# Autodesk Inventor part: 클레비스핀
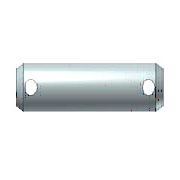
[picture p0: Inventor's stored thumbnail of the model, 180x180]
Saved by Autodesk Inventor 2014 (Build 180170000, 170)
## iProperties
IsCustomPart: 1
Created: 2012-02
Part Number: 클레비스핀
Material: 강철
Description: 머리가 없는 클레비스 핀 B
Document SubType Name: Modeling
Standard: ISO 2340
Designer: mduedu
Standard Revision: Second edition 1986-11-01
Standards Organization: ISO
Language: ko-KR
Size Designation: B - 8 x 45
Categories: <MemberInstance><Categories><Category DisplayName="조임쇠" InternalName="e4da775c-781d-43d5-af7c-5136215cf5a6" Mnemonic="FSTN"><Category DisplayName="핀" InternalNa
Density: 7.85 g/cm^3
Appearance: Steel
Author: mduedu
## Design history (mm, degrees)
sketch "스케치1"
  geometry: L1 (-4.5, 0)-(-4.5, 4); L2 (-4.5, 4)-(40.5, 4); L3 (40.5, 4)-(40.5, 0); L4 (-4.5, 0)-(40.5, 0); L5 (0, -1.46)-(0, 3.16) reference; L6 (-6.4, 0)-(18.8, 0) reference; C1 r 1 at (-1, 0); C2 r 1 at (37, 0)
  constraints: 8 end point, 2 centre point, 2 perpendicular, 2 point on line, 1 collinear, 1 parallel, 1 tangent, 1 vertical
  dimensions: "d0" = 8 diameter of L2 L4 (= NND); "d1" = 45 distance of L1.end L2.end (= NLG); "d2" = 3.5 distance from line of L1 C1.centre (= DIST1); "d3" = 3.5 distance from line of L3 C2.centre (= DIST2); "d4" = 2 diameter of C1 (= BOR1); "d5" = 2 diameter of C2 (= BOR2)
revolve "본체" stored, may be unused: angle "d7" = 90 deg
extrude "구멍1" cut sketch "스케치1" taper "d6" = 0 deg; stored distance "d8" = 10
extrude "구멍2" cut sketch "스케치1" taper "d13" = 0 deg; stored distance "d14" = 10
node "작업 평면5"
body "Solid1"
chamfer "모따기2" distance "d9" = 2 (= PHH2); stored, may be unused: angle "d10" = 30 deg (= FAWI2), second distance "d40" = 2 (= PHH2)
chamfer "모따기1" distance "d11" = 2 (= PHH1); stored, may be unused: angle "d12" = 30 deg (= FAWI1), second distance "d41" = 2 (= PHH1)
workaxis "Work Axis1"
workaxis "Work Axis2"
workplane "Work Plane1"
other parameters: "NLG" = 45 [user parameter; used in 1 equation term], "NND" = 8 [user parameter; used in 1 equation term], "PHH1" = 2 [user parameter; used in 3 equation terms], "PHH2" = 2 (= PHH1) [user parameter; used in 2 equation terms], "FAWI1" = 30 deg [user parameter; used in 1 equation term], "FAWI2" = 30 deg [user parameter; used in 1 equation term], "DIST1" = 3.5 [user parameter; used in 4 equation terms], "DIST2" = 3.5 (= DIST1) [user parameter; used in 1 equation term], "BOR1" = 2 [user parameter; used in 4 equation terms], "BOR2" = 2 (= BOR1) [user parameter; used in 1 equation term], "d15" = 0, "d42" = 0, "d43" = 0, "d44" = -4.5 (= -0.5 x BOR1 - DIST1), "d45" = -4.5 (= -0.5 x BOR1 - DIST1), "d47" = 0, "d48" = 0, "d49" = 0, "d50" = 0, "d51" = 0, "d52" = 0
